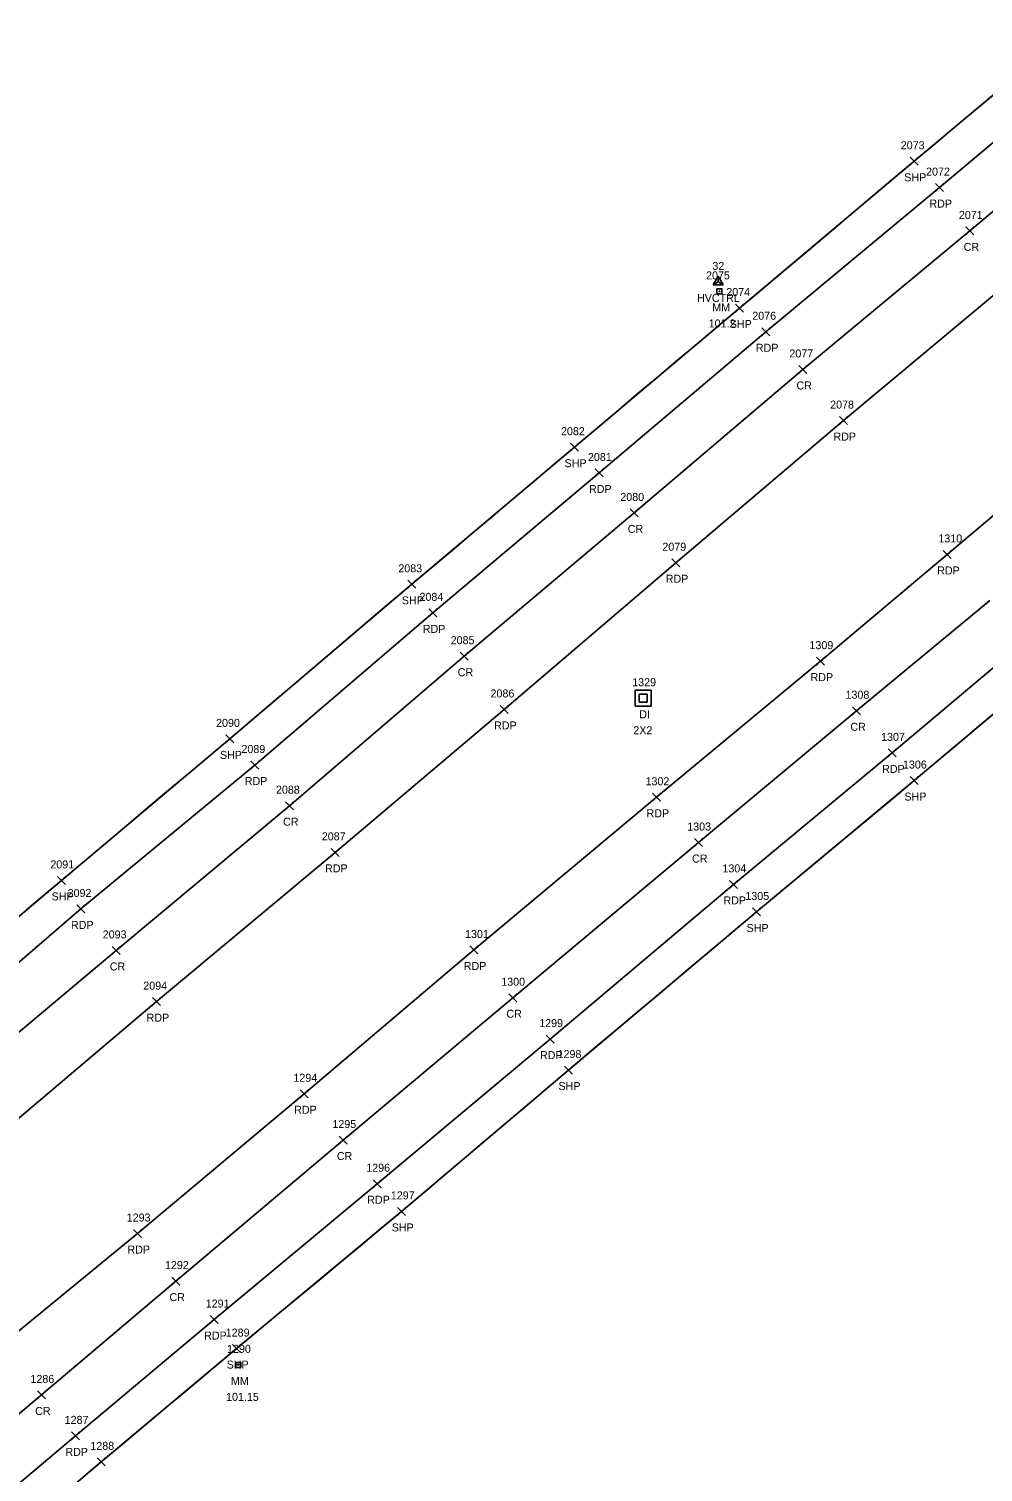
# Model space of a CAD drawing. Extents: x 1472022 to 1479249, y 777216 to 786527.
# Drawn here: x 1472455.3 to 1472693.8, y 777538.1 to 777898.8 of the extents above; entities that cross this region are included whole.
import ezdxf

# ---------------------------------------------------------------- set-up
doc = ezdxf.new("R2010")
doc.units = 0
for name, color, linetype in [('C_A', 7, 'Continuous'), ('C_I', 7, 'Continuous'), ('CPSM', 7, 'Continuous'), ('D_A', 7, 'Continuous'), ('D_C', 7, 'Continuous'), ('D_I', 7, 'Continuous'), ('DS', 7, 'Continuous'), ('LSOGP', 7, 'Continuous'), ('P_A', 7, 'Continuous'), ('P_I', 7, 'Continuous'), ('P_TIC', 7, 'Continuous'), ('PET', 7, 'Continuous'), ('PRC', 7, 'Continuous'), ('PSP', 7, 'Continuous'), ('S_A', 7, 'Continuous'), ('S_C', 7, 'Continuous'), ('S_I', 7, 'Continuous'), ('SRM', 7, 'Continuous')]:
    doc.layers.add(name, color=color, linetype=linetype)

msp = doc.modelspace()

# ---------------------------------------------------------------- linework, layer by layer
at = {"layer": 'CPSM'}
for p, q in [((1472626.33, 777834.83), (1472627.58, 777836.99)), ((1472628.83, 777834.83), (1472627.58, 777836.99)), ((1472627.58, 777835.55), (1472627.58, 777836.99)), ((1472626.33, 777834.83), (1472627.58, 777835.55)), ((1472626.33, 777834.83), (1472628.83, 777834.83)), ((1472627.58, 777835.55), (1472627.58, 777835.55)), ((1472627.58, 777835.55), (1472628.83, 777834.83))]:
    msp.add_line(p, q, dxfattribs=at)
at = {"layer": 'DS'}
for p, q in [((1472606.78, 777733.51), (1472610.78, 777733.51)), ((1472606.78, 777729.51), (1472606.78, 777733.51)), ((1472607.78, 777730.51), (1472607.78, 777732.51)), ((1472607.78, 777732.51), (1472609.78, 777732.51)), ((1472608.79, 777731.51), (1472608.79, 777731.51)), ((1472608.79, 777731.51), (1472608.79, 777731.51)), ((1472609.78, 777732.51), (1472609.78, 777730.51)), ((1472610.78, 777733.51), (1472610.78, 777729.51)), ((1472610.78, 777729.51), (1472606.78, 777729.51)), ((1472609.78, 777730.51), (1472607.78, 777730.51))]:
    msp.add_line(p, q, dxfattribs=at)
at = {"layer": 'LSOGP'}
for points in [[(1472696.29, 777882.23), (1472691.36, 777878.1), (1472686.42, 777873.96), (1472681.49, 777869.82), (1472676.55, 777865.69), (1472671.1, 777861.1), (1472665.65, 777856.52), (1472660.19, 777851.94), (1472654.74, 777847.35), (1472649.29, 777842.77), (1472643.84, 777838.19), (1472638.39, 777833.6), (1472632.93, 777829.02), (1472627.77, 777824.67), (1472622.61, 777820.33), (1472617.44, 777815.98), (1472612.28, 777811.64), (1472607.11, 777807.29), (1472601.95, 777802.95), (1472596.79, 777798.6), (1472591.62, 777794.25), (1472586.54, 777789.97), (1472581.46, 777785.68), (1472576.37, 777781.4), (1472571.29, 777777.11), (1472566.21, 777772.83), (1472561.12, 777768.55), (1472556.04, 777764.26), (1472550.96, 777759.98), (1472545.27, 777755.15), (1472539.59, 777750.32), (1472533.9, 777745.49), (1472528.22, 777740.66), (1472522.54, 777735.84), (1472516.85, 777731.01), (1472511.17, 777726.18), (1472505.48, 777721.35), (1472500.22, 777716.93), (1472494.96, 777712.51), (1472489.7, 777708.09), (1472484.44, 777703.67), (1472479.18, 777699.25), (1472473.92, 777694.83), (1472468.66, 777690.41), (1472463.4, 777685.99), (1472459.03, 777682.31), (1472454.67, 777678.64)], [(1472469.01, 777537.01), (1472473.33, 777540.69), (1472477.56, 777544.23), (1472481.79, 777547.77), (1472486.02, 777551.3), (1472490.25, 777554.84), (1472494.48, 777558.38), (1472498.71, 777561.92), (1472502.94, 777565.46), (1472507.17, 777569), (1472512.33, 777573.28), (1472517.48, 777577.56), (1472522.64, 777581.85), (1472527.8, 777586.13), (1472532.96, 777590.41), (1472538.12, 777594.7), (1472543.28, 777598.98), (1472548.43, 777603.27), (1472553.64, 777607.68), (1472558.86, 777612.1), (1472564.07, 777616.52), (1472569.28, 777620.93), (1472574.49, 777625.35), (1472579.7, 777629.76), (1472584.91, 777634.18), (1472590.12, 777638.6), (1472596, 777643.54), (1472601.87, 777648.47), (1472607.75, 777653.41), (1472613.62, 777658.35), (1472619.5, 777663.29), (1472625.38, 777668.23), (1472631.25, 777673.16), (1472637.13, 777678.1), (1472642.06, 777682.21), (1472647, 777686.31), (1472651.93, 777690.42), (1472656.86, 777694.52), (1472661.8, 777698.63), (1472666.73, 777702.73), (1472671.66, 777706.83), (1472676.6, 777710.94), (1472680.66, 777714.35), (1472684.72, 777717.76), (1472688.77, 777721.17), (1472692.83, 777724.58), (1472696.89, 777727.99)]]:
    msp.add_lwpolyline(points, dxfattribs=at)
at = {"layer": 'P_TIC'}
for points in [[(1472675.55, 777864.69), (1472677.55, 777866.69)], [(1472677.55, 777864.69), (1472675.55, 777866.69)], [(1472681.88, 777858.11), (1472683.88, 777860.11)], [(1472683.88, 777858.11), (1472681.88, 777860.11)], [(1472689.51, 777847.29), (1472691.51, 777849.29)], [(1472691.51, 777847.29), (1472689.51, 777849.29)], [(1472631.93, 777828.02), (1472633.93, 777830.02)], [(1472633.93, 777828.02), (1472631.93, 777830.02)], [(1472638.49, 777822.09), (1472640.49, 777824.09)], [(1472640.49, 777822.09), (1472638.49, 777824.09)], [(1472647.7, 777812.67), (1472649.7, 777814.67)], [(1472649.7, 777812.67), (1472647.7, 777814.67)], [(1472657.9, 777799.89), (1472659.9, 777801.89)], [(1472659.9, 777799.89), (1472657.9, 777801.89)], [(1472590.62, 777793.25), (1472592.62, 777795.25)], [(1472592.62, 777793.25), (1472590.62, 777795.25)], [(1472596.79, 777786.8), (1472598.79, 777788.8)], [(1472598.79, 777786.8), (1472596.79, 777788.8)], [(1472605.54, 777776.82), (1472607.54, 777778.82)], [(1472607.54, 777776.82), (1472605.54, 777778.82)], [(1472683.83, 777766.44), (1472685.83, 777768.44)], [(1472685.83, 777766.44), (1472683.83, 777768.44)], [(1472615.97, 777764.37), (1472617.97, 777766.37)], [(1472617.97, 777764.37), (1472615.97, 777766.37)], [(1472549.96, 777758.98), (1472551.96, 777760.98)], [(1472551.96, 777758.98), (1472549.96, 777760.98)], [(1472555.24, 777751.85), (1472557.24, 777753.85)], [(1472557.24, 777751.85), (1472555.24, 777753.85)], [(1472563.04, 777741.02), (1472565.04, 777743.02)], [(1472565.04, 777741.02), (1472563.04, 777743.02)], [(1472652.17, 777739.78), (1472654.17, 777741.78)], [(1472654.17, 777739.78), (1472652.17, 777741.78)], [(1472573.07, 777727.71), (1472575.07, 777729.71)], [(1472575.07, 777727.71), (1472573.07, 777729.71)], [(1472661.17, 777727.39), (1472663.17, 777729.39)], [(1472663.17, 777727.39), (1472661.17, 777729.39)], [(1472504.48, 777720.35), (1472506.48, 777722.35)], [(1472506.48, 777720.35), (1472504.48, 777722.35)], [(1472670.07, 777716.85), (1472672.07, 777718.85)], [(1472672.07, 777716.85), (1472670.07, 777718.85)], [(1472510.74, 777713.82), (1472512.74, 777715.82)], [(1472512.74, 777713.82), (1472510.74, 777715.82)], [(1472675.6, 777709.94), (1472677.6, 777711.94)], [(1472677.6, 777709.94), (1472675.6, 777711.94)], [(1472611.18, 777705.76), (1472613.18, 777707.76)], [(1472613.18, 777705.76), (1472611.18, 777707.76)], [(1472519.37, 777703.66), (1472521.37, 777705.66)], [(1472521.37, 777703.66), (1472519.37, 777705.66)], [(1472621.61, 777694.45), (1472623.61, 777696.45)], [(1472623.61, 777694.45), (1472621.61, 777696.45)], [(1472530.82, 777692), (1472532.82, 777694)], [(1472532.82, 777692), (1472530.82, 777694)], [(1472462.4, 777684.99), (1472464.4, 777686.99)], [(1472464.4, 777684.99), (1472462.4, 777686.99)], [(1472630.41, 777683.99), (1472632.41, 777685.99)], [(1472632.41, 777683.99), (1472630.41, 777685.99)], [(1472467.29, 777677.86), (1472469.29, 777679.86)], [(1472469.29, 777677.86), (1472467.29, 777679.86)], [(1472636.13, 777677.1), (1472638.13, 777679.1)], [(1472638.13, 777677.1), (1472636.13, 777679.1)], [(1472476.06, 777667.49), (1472478.06, 777669.49)], [(1472478.06, 777667.49), (1472476.06, 777669.49)], [(1472565.51, 777667.6), (1472567.51, 777669.6)], [(1472567.51, 777667.6), (1472565.51, 777669.6)], [(1472486.2, 777654.69), (1472488.2, 777656.69)], [(1472488.2, 777654.69), (1472486.2, 777656.69)], [(1472575.2, 777655.67), (1472577.2, 777657.67)], [(1472577.2, 777655.67), (1472575.2, 777657.67)], [(1472584.53, 777645.33), (1472586.53, 777647.33)], [(1472586.53, 777645.33), (1472584.53, 777647.33)], [(1472589.12, 777637.6), (1472591.12, 777639.6)], [(1472591.12, 777637.6), (1472589.12, 777639.6)], [(1472523.08, 777631.67), (1472525.08, 777633.67)], [(1472525.08, 777631.67), (1472523.08, 777633.67)], [(1472532.82, 777620.11), (1472534.82, 777622.11)], [(1472534.82, 777620.11), (1472532.82, 777622.11)], [(1472541.35, 777609.19), (1472543.35, 777611.19)], [(1472543.35, 777609.19), (1472541.35, 777611.19)], [(1472547.43, 777602.27), (1472549.43, 777604.27)], [(1472549.43, 777602.27), (1472547.43, 777604.27)], [(1472481.41, 777596.75), (1472483.41, 777598.75)], [(1472483.41, 777596.75), (1472481.41, 777598.75)], [(1472490.98, 777584.86), (1472492.98, 777586.86)], [(1472492.98, 777584.86), (1472490.98, 777586.86)], [(1472500.59, 777575.25), (1472502.59, 777577.25)], [(1472502.59, 777575.25), (1472500.59, 777577.25)], [(1472506.17, 777568), (1472508.17, 777570)], [(1472508.17, 777568), (1472506.17, 777570)], [(1472457.4, 777556.41), (1472459.4, 777558.41)], [(1472459.4, 777556.41), (1472457.4, 777558.41)], [(1472465.91, 777546.18), (1472467.91, 777548.18)], [(1472467.91, 777546.18), (1472465.91, 777548.18)], [(1472472.33, 777539.69), (1472474.33, 777541.69)], [(1472474.33, 777539.69), (1472472.33, 777541.69)]]:
    msp.add_lwpolyline(points, dxfattribs=at)
at = {"layer": 'PET'}
for points in [[(1472722.68, 777892.48), (1472682.88, 777859.11), (1472639.49, 777823.09), (1472597.79, 777787.8), (1472556.24, 777752.85), (1472511.74, 777714.82), (1472468.29, 777678.86), (1472434.09, 777649.49), (1472400.54, 777621.47), (1472363.79, 777590.54), (1472325.19, 777558.4), (1472281.62, 777521.48), (1472234.5, 777482.07), (1472193.79, 777447.69), (1472152.16, 777412.75), (1472108.18, 777375.84), (1472065.2, 777340.27), (1472030.56, 777311.04)], [(1472700.25, 777835.4), (1472658.9, 777800.89), (1472616.97, 777765.37), (1472574.07, 777728.71), (1472531.82, 777693), (1472487.2, 777655.69), (1472451.66, 777625.63), (1472418.21, 777598.11), (1472383.18, 777567.96), (1472344.18, 777535.52), (1472301.56, 777499.89), (1472253.31, 777459.47), (1472213.07, 777426.05), (1472170.94, 777391.85), (1472126.39, 777354.27), (1472084.25, 777318.79), (1472048.65, 777289.11)], [(1472078.03, 777257.61), (1472120.14, 777293.33), (1472164.04, 777330.1), (1472206.26, 777365.72), (1472247.19, 777400.1), (1472281.71, 777428.77), (1472322.39, 777463.14), (1472366.75, 777500.3), (1472413.17, 777539.86), (1472444.63, 777566.82), (1472482.41, 777597.75), (1472524.08, 777632.67), (1472566.51, 777668.6), (1472612.18, 777706.76), (1472653.17, 777740.78), (1472684.83, 777767.44), (1472722.55, 777799.22)], [(1472096.13, 777235.76), (1472138.04, 777271.25), (1472193.56, 777316.24), (1472224.84, 777343.8), (1472265.41, 777377.88), (1472299.98, 777407.09), (1472340.04, 777440.63), (1472384.1, 777477.91), (1472432.66, 777518.35), (1472466.91, 777547.18), (1472501.59, 777576.25), (1472542.35, 777610.19), (1472585.53, 777646.33), (1472631.41, 777684.99), (1472671.07, 777717.85), (1472704.16, 777745.65)]]:
    msp.add_lwpolyline(points, dxfattribs=at)
at = {"layer": 'PRC'}
for points in [[(1472731.22, 777882.43), (1472690.51, 777848.29), (1472648.7, 777813.67), (1472606.54, 777777.82), (1472564.04, 777742.02), (1472520.37, 777704.66), (1472477.06, 777668.49), (1472442.15, 777639.21), (1472408.33, 777611.04), (1472372.78, 777580.72), (1472334.64, 777548.84), (1472290.86, 777511.89), (1472242.9, 777471.7), (1472202.68, 777437.35), (1472161.87, 777403.07), (1472116.61, 777365.36), (1472074.99, 777330.82), (1472039.59, 777301.03)], [(1472087.18, 777245.54), (1472129.69, 777281.74), (1472174.12, 777318.82), (1472215.99, 777354.07), (1472256.54, 777388.59), (1472291.65, 777417.38), (1472331.92, 777451.29), (1472376.32, 777488.53), (1472423.47, 777528.02), (1472458.4, 777557.41), (1472491.98, 777585.86), (1472533.82, 777621.11), (1472576.2, 777656.67), (1472622.61, 777695.45), (1472662.17, 777728.39), (1472695.49, 777755.92)]]:
    msp.add_lwpolyline(points, dxfattribs=at)
at = {"layer": 'PSP'}
for points in [[(1472716.04, 777898.78), (1472676.55, 777865.69), (1472632.93, 777829.02), (1472591.62, 777794.25), (1472550.96, 777759.98), (1472505.48, 777721.35), (1472463.4, 777685.99), (1472428.49, 777656.59), (1472394.27, 777628.16), (1472357.91, 777597.61), (1472319.5, 777565.03), (1472275.88, 777528.71), (1472228.56, 777488.93), (1472187.83, 777454.7), (1472146.55, 777420.08), (1472102.55, 777382.93), (1472060.05, 777347.18), (1472024.71, 777317.56)], [(1472102.03, 777228.49), (1472145.67, 777262.13), (1472190, 777302.18), (1472230.73, 777336.4), (1472271.49, 777370.54), (1472305.4, 777399.26), (1472347.11, 777433.78), (1472390.53, 777470.46), (1472438.76, 777511.25), (1472473.33, 777540.69), (1472507.17, 777569), (1472548.43, 777603.27), (1472590.12, 777638.6), (1472637.13, 777678.1), (1472676.6, 777710.94), (1472709.07, 777738.21)]]:
    msp.add_lwpolyline(points, dxfattribs=at)
at = {"layer": 'SRM'}
for points in [[(1472627.27, 777833.79), (1472628.52, 777833.79), (1472628.52, 777832.54), (1472627.27, 777832.54)], [(1472506.96, 777565.55), (1472508.21, 777565.55), (1472508.21, 777564.3), (1472506.96, 777564.3)]]:
    msp.add_lwpolyline(points, close=True, dxfattribs=at)
for centre in [(1472627.89, 777833.17), (1472507.58, 777564.93)]:
    msp.add_circle(centre, 0.0833, dxfattribs=at)

# ---------------------------------------------------------------- texts
at = {"layer": 'C_A'}
msp.add_text('HVCTRL', height=2, dxfattribs=at).set_placement((1472622.28, 777830.55))
at = {"layer": 'C_I'}
msp.add_text('32', height=2, dxfattribs=at).set_placement((1472626.12, 777838.55))
at = {"layer": 'D_A'}
msp.add_text('DI', height=2, dxfattribs=at).set_placement((1472607.84, 777726.51))
at = {"layer": 'D_C'}
msp.add_text('2X2', height=2, dxfattribs=at).set_placement((1472606.36, 777722.51))
at = {"layer": 'D_I'}
msp.add_text('1329', height=2, dxfattribs=at).set_placement((1472606.09, 777734.51))
at = {"layer": 'P_A'}
for s, p in [('SHP', (1472674.08, 777860.69)), ('RDP', (1472680.37, 777854.11)), ('CR', (1472688.94, 777843.29)), ('SHP', (1472630.47, 777824.02)), ('RDP', (1472636.98, 777818.09)), ('CR', (1472647.14, 777808.67)), ('RDP', (1472656.39, 777795.89)), ('SHP', (1472589.16, 777789.25)), ('RDP', (1472595.28, 777782.8)), ('CR', (1472604.97, 777772.82)), ('RDP', (1472682.31, 777762.44)), ('RDP', (1472614.45, 777760.37)), ('SHP', (1472548.49, 777754.98)), ('RDP', (1472553.73, 777747.85)), ('CR', (1472562.47, 777737.02)), ('RDP', (1472650.66, 777735.78)), ('RDP', (1472571.56, 777723.71)), ('CR', (1472660.6, 777723.39)), ('SHP', (1472503.02, 777716.35)), ('RDP', (1472668.55, 777712.85)), ('RDP', (1472509.23, 777709.82)), ('SHP', (1472674.13, 777705.94)), ('RDP', (1472609.67, 777701.76)), ('CR', (1472518.8, 777699.66)), ('CR', (1472621.04, 777690.45)), ('RDP', (1472529.31, 777688)), ('SHP', (1472460.93, 777680.99)), ('RDP', (1472628.89, 777679.99)), ('RDP', (1472465.78, 777673.86)), ('SHP', (1472634.67, 777673.1)), ('CR', (1472475.49, 777663.49)), ('RDP', (1472563.99, 777663.6)), ('RDP', (1472484.69, 777650.69)), ('CR', (1472574.64, 777651.67)), ('RDP', (1472583.02, 777641.33)), ('SHP', (1472587.65, 777633.6)), ('RDP', (1472521.57, 777627.67)), ('CR', (1472532.25, 777616.11)), ('RDP', (1472539.84, 777605.19)), ('SHP', (1472545.97, 777598.27)), ('RDP', (1472479.9, 777592.75)), ('CR', (1472490.41, 777580.86)), ('RDP', (1472499.08, 777571.25)), ('SHP', (1472504.7, 777564)), ('CR', (1472456.83, 777552.41)), ('RDP', (1472464.39, 777542.18))]:
    msp.add_text(s, height=2, dxfattribs=at).set_placement(p)
at = {"layer": 'P_I'}
for s, p in [('2073', (1472673.21, 777868.69)), ('2072', (1472679.54, 777862.11)), ('2071', (1472687.74, 777851.29)), ('2074', (1472629.6, 777832.02)), ('2076', (1472636.1, 777826.09)), ('2077', (1472645.37, 777816.67)), ('2078', (1472655.56, 777803.89)), ('2082', (1472588.28, 777797.25)), ('2081', (1472595.02, 777790.8)), ('2080', (1472603.11, 777780.82)), ('1310', (1472682.61, 777770.44)), ('2079', (1472613.62, 777768.37)), ('2083', (1472547.62, 777762.98)), ('2084', (1472552.9, 777755.85)), ('2085', (1472560.7, 777745.02)), ('1309', (1472650.39, 777743.78)), ('2086', (1472570.67, 777731.71)), ('1308', (1472659.4, 777731.39)), ('2090', (1472502.06, 777724.35)), ('1307', (1472668.29, 777720.85)), ('2089', (1472508.4, 777717.82)), ('1306', (1472673.77, 777713.94)), ('1302', (1472609.41, 777709.76)), ('2088', (1472517.03, 777707.66)), ('1303', (1472619.84, 777698.45)), ('2087', (1472528.48, 777696)), ('2091', (1472460.63, 777688.99)), ('1304', (1472628.63, 777687.99)), ('2092', (1472464.95, 777681.86)), ('1305', (1472634.36, 777681.1)), ('2093', (1472473.72, 777671.49)), ('1301', (1472564.3, 777671.6)), ('2094', (1472483.86, 777658.69)), ('1300', (1472573.34, 777659.67)), ('1299', (1472582.83, 777649.33)), ('1298', (1472587.43, 777641.6)), ('1294', (1472521.39, 777635.67)), ('1295', (1472531.13, 777624.11)), ('1296', (1472539.6, 777613.19)), ('1297', (1472545.74, 777606.27)), ('1293', (1472479.72, 777600.75)), ('1292', (1472489.28, 777588.86)), ('1291', (1472499.47, 777579.25)), ('1289', (1472504.47, 777572)), ('1286', (1472455.65, 777560.41)), ('1287', (1472464.21, 777550.18)), ('1288', (1472470.63, 777543.69))]:
    msp.add_text(s, height=2, dxfattribs=at).set_placement(p)
at = {"layer": 'S_A'}
for p in [(1472626.08, 777828.17), (1472505.77, 777559.93)]:
    msp.add_text('MM', height=2, dxfattribs=at).set_placement(p)
at = {"layer": 'S_C'}
for s, p in [('101.2', (1472625.2, 777824.17)), ('101.15', (1472504.56, 777555.93))]:
    msp.add_text(s, height=2, dxfattribs=at).set_placement(p)
at = {"layer": 'S_I'}
for s, p in [('2075', (1472624.55, 777836.17)), ('1290', (1472504.8, 777567.93))]:
    msp.add_text(s, height=2, dxfattribs=at).set_placement(p)

doc.saveas('drawing.dxf')
